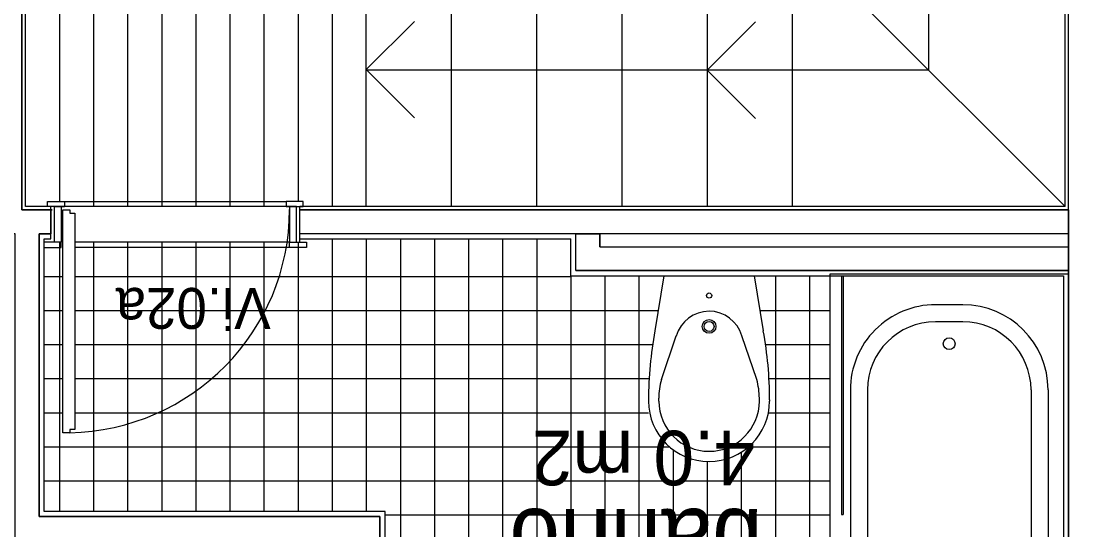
# Model space of a CAD drawing. Extents: x 1278 to 1356, y -253.7 to -224.
# Drawn here: x 1336.931 to 1340.025, y -239.375 to -237.882 of the extents above; entities that cross this region are included whole.
import ezdxf

# ---------------------------------------------------------------- set-up
doc = ezdxf.new("R2010")
doc.units = 0
for name, color, linetype in [('Level 1', 7, 'Continuous'), ('Level 10', 7, 'Continuous'), ('Level 11', 7, 'Continuous'), ('Level 13', 7, 'Continuous'), ('Level 2', 7, 'Continuous'), ('Level 36', 7, 'Continuous'), ('Level 4', 7, 'Continuous'), ('Level 40', 7, 'Continuous'), ('Level 60', 7, 'Continuous'), ('Level 65', 7, 'Continuous'), ('Level 66', 7, 'Continuous'), ('Level 67', 7, 'Continuous')]:
    doc.layers.add(name, color=color, linetype=linetype)

msp = doc.modelspace()

# ---------------------------------------------------------------- linework, layer by layer
at = {"layer": 'Level 1'}
for p, q in [((1340.0033, -238.4357), (1340.0033, -235.7107)), ((1336.9333, -238.4357), (1336.9333, -236.6557)), ((1337.0183, -238.4357), (1336.9333, -238.4357)), ((1337.0183, -238.5207), (1337.0183, -238.4257)), ((1337.7483, -238.5307), (1337.7483, -238.4257)), ((1340.0033, -238.4357), (1337.7483, -238.4357)), ((1336.9833, -239.3357), (1336.9833, -238.5057)), ((1336.9833, -238.5057), (1337.0183, -238.5057)), ((1338.5583, -238.5057), (1337.7483, -238.5057)), ((1340.0033, -238.5057), (1338.6283, -238.5057)), ((1340.0033, -238.614), (1340.0033, -240.234)), ((1337.9833, -239.3357), (1336.9833, -239.3357)), ((1337.9833, -240.234), (1337.9833, -239.3357))]:
    msp.add_line(p, q, dxfattribs=at)
at = {"layer": 'Level 10'}
for p, q in [((1337.0433, -235.7207), (1337.0433, -238.4107)), ((1337.1433, -235.7207), (1337.1433, -238.4257)), ((1337.2433, -235.7207), (1337.2433, -238.4257)), ((1337.3433, -235.7207), (1337.3433, -238.4257)), ((1337.4433, -235.7207), (1337.4433, -238.4257)), ((1337.5433, -235.7207), (1337.5433, -238.4257)), ((1337.6433, -235.7207), (1337.6433, -238.4257)), ((1337.7433, -235.7207), (1337.7433, -238.4107)), ((1337.8433, -236.6557), (1337.8433, -238.4257)), ((1337.7083, -238.4257), (1337.0583, -238.4257)), ((1337.8433, -238.5207), (1337.8433, -239.3207)), ((1337.9433, -238.5207), (1337.9433, -239.3207)), ((1338.0433, -238.5207), (1338.0433, -239.669)), ((1338.1433, -238.5207), (1338.1433, -239.669)), ((1338.2433, -238.5207), (1338.2433, -239.669)), ((1338.3433, -238.5207), (1338.3433, -239.669)), ((1338.4433, -238.5207), (1338.4433, -239.669)), ((1337.0433, -238.5307), (1337.0433, -239.3207)), ((1337.7183, -238.5307), (1337.0883, -238.5307)), ((1337.1433, -238.5307), (1337.1433, -239.3207)), ((1337.2433, -238.5307), (1337.2433, -239.3207)), ((1337.3433, -238.5307), (1337.3433, -239.3207)), ((1337.4433, -238.5307), (1337.4433, -239.3207)), ((1337.5433, -238.5307), (1337.5433, -239.3207)), ((1337.6433, -238.5307), (1337.6433, -239.3207)), ((1337.7433, -238.5307), (1337.7433, -239.3207)), ((1336.9983, -238.6307), (1337.0533, -238.6307)), ((1337.0883, -238.6307), (1338.5433, -238.6307)), ((1338.5433, -238.629), (1338.5433, -239.669)), ((1338.6433, -238.629), (1338.6433, -240.219)), ((1338.7433, -238.629), (1338.7433, -240.219)), ((1339.1433, -238.629), (1339.1433, -240.219)), ((1339.2433, -238.629), (1339.2433, -240.219)), ((1336.9983, -238.7307), (1337.0533, -238.7307)), ((1337.0883, -238.7307), (1338.7999, -238.7307)), ((1339.098, -238.7307), (1339.3033, -238.7307)), ((1336.9983, -238.8307), (1337.0533, -238.8307)), ((1337.0883, -238.8307), (1338.7834, -238.8307)), ((1339.1145, -238.8307), (1339.3033, -238.8307)), ((1336.9983, -238.9307), (1337.0533, -238.9307)), ((1337.0883, -238.9307), (1338.7732, -238.9307)), ((1339.1247, -238.9307), (1339.3033, -238.9307)), ((1336.9983, -239.0307), (1337.0533, -239.0307)), ((1337.0883, -239.0307), (1338.7714, -239.0307)), ((1339.1231, -239.0307), (1339.3033, -239.0307)), ((1336.9983, -239.1307), (1338.8328, -239.1307)), ((1338.8433, -239.1391), (1338.8433, -239.7067)), ((1339.0433, -239.1468), (1339.0433, -239.7067)), ((1339.065, -239.1307), (1339.3033, -239.1307)), ((1338.9433, -239.1739), (1338.9433, -239.6759)), ((1336.9983, -239.2307), (1339.3033, -239.2307)), ((1337.9983, -239.3307), (1339.3033, -239.3307))]:
    msp.add_line(p, q, dxfattribs=at)
at = {"layer": 'Level 11'}
for p, q in [((1338.8166, -238.629), (1338.79, -238.791)), ((1338.8166, -238.629), (1339.0812, -238.629)), ((1339.0812, -238.629), (1339.1079, -238.791)), ((1340.0033, -238.624), (1339.3033, -238.624)), ((1339.3033, -238.624), (1339.3033, -240.224)), ((1340.0033, -238.624), (1340.0033, -240.224)), ((1339.6933, -238.714), (1339.6133, -238.714)), ((1339.6933, -238.764), (1339.6133, -238.764)), ((1338.8091, -238.9335), (1338.8528, -238.8055)), ((1339.0887, -238.9335), (1339.0451, -238.8055)), ((1338.7714, -238.9931), (1338.7714, -238.9968)), ((1338.8014, -238.9965), (1338.8014, -238.9884)), ((1339.0964, -238.9965), (1339.0964, -238.9884)), ((1339.1264, -238.9931), (1339.1264, -238.9968)), ((1339.3633, -238.964), (1339.3633, -240.014)), ((1339.4133, -238.964), (1339.4133, -239.914)), ((1339.8933, -238.964), (1339.8933, -239.914)), ((1339.9433, -238.964), (1339.9433, -240.014))]:
    msp.add_line(p, q, dxfattribs=at)
for centre, radius in [((1338.9489, -238.687), 0.00766), ((1338.9489, -238.7778), 0.02), ((1338.9489, -238.7778), 0.0146), ((1339.6533, -238.8284), 0.0173)]:
    msp.add_circle(centre, radius, dxfattribs=at)
for centre, radius, start, end in [((1339.6133, -238.964), 0.25, 89.9999, 180), ((1339.6933, -238.964), 0.25, 0.0001, 90.0001), ((1338.9489, -238.833), 0.1, 15.9317, 164.1953), ((1339.6133, -238.964), 0.2, 90, 180), ((1339.6933, -238.964), 0.2, 360, 90), ((1339.0014, -238.9884), 0.2, 164.0693, 180.0006), ((1338.8964, -238.9884), 0.2, 0.0017, 15.9319), ((1338.9489, -238.9965), 0.1775, 180.0002, 359.9999), ((1338.9489, -238.9965), 0.1475, 180.0002, 359.9999)]:
    msp.add_arc(centre, radius, start, end, dxfattribs=at)
for centre, major_axis, start_param, end_param in [((1340.1714, -238.9931), (-1.4, 0), 6.120269, 6.283187), ((1337.7264, -238.9931), (1.4, 0), 6.283183, 6.446102)]:
    msp.add_ellipse(centre, major_axis=major_axis, ratio=0.88995, start_param=start_param, end_param=end_param, dxfattribs=at)
at = {"layer": 'Level 13'}
for p, q in [((1337.0083, -238.4107), (1337.0583, -238.4107)), ((1337.0083, -238.4257), (1337.0083, -238.4107)), ((1337.0583, -238.4257), (1337.0083, -238.4257)), ((1337.0283, -238.5307), (1337.0283, -238.4257)), ((1337.0283, -238.4257), (1337.0583, -238.4257)), ((1337.0483, -238.4257), (1337.0483, -238.5307)), ((1337.0533, -239.0901), (1337.0533, -238.4351)), ((1337.0533, -238.4351), (1337.0733, -238.4351)), ((1337.0583, -238.4107), (1337.0583, -238.4257)), ((1337.0733, -238.4351), (1337.0733, -238.4451)), ((1337.7583, -238.4107), (1337.7083, -238.4107)), ((1337.7083, -238.4107), (1337.7083, -238.4257)), ((1337.7383, -238.4257), (1337.7083, -238.4257)), ((1337.7083, -238.4257), (1337.7583, -238.4257)), ((1337.7183, -238.4257), (1337.7183, -238.5307)), ((1337.7383, -238.5307), (1337.7383, -238.4257)), ((1337.7583, -238.4257), (1337.7583, -238.4107)), ((1337.0733, -238.4451), (1337.0883, -238.4451)), ((1337.0883, -238.4451), (1337.0883, -239.0801)), ((1337.0483, -238.5307), (1336.9983, -238.5307)), ((1336.9983, -238.5457), (1337.0483, -238.5457)), ((1337.0483, -238.5307), (1337.0283, -238.5307)), ((1337.0483, -238.5457), (1337.0483, -238.5307)), ((1337.7183, -238.5457), (1337.7183, -238.5307)), ((1337.7183, -238.5307), (1337.7383, -238.5307)), ((1337.7183, -238.5307), (1337.7683, -238.5307)), ((1337.7683, -238.5457), (1337.7183, -238.5457)), ((1337.7683, -238.5307), (1337.7683, -238.5457)), ((1337.0733, -239.0801), (1337.0733, -239.0898)), ((1337.0883, -239.0801), (1337.0733, -239.0801)), ((1337.0733, -239.0901), (1337.0533, -239.0901))]:
    msp.add_line(p, q, dxfattribs=at)
at = {"layer": 'Level 2'}
for p, q in [((1339.5933, -238.0257), (1339.5933, -237.2257)), ((1339.1933, -237.6257), (1339.9933, -238.4257)), ((1337.9433, -238.424), (1337.9433, -237.6557)), ((1338.1933, -238.424), (1338.1933, -237.6557)), ((1338.4433, -238.424), (1338.4433, -237.6557)), ((1338.6933, -237.6557), (1338.6933, -238.424)), ((1338.9433, -237.654), (1338.9433, -238.424)), ((1339.1933, -238.4257), (1339.1933, -237.6557)), ((1338.0847, -237.8826), (1337.9433, -238.024)), ((1339.0847, -237.8843), (1338.9433, -238.0257)), ((1338.0847, -238.1654), (1337.9433, -238.024)), ((1339.5933, -238.0257), (1337.9433, -238.0257)), ((1339.0847, -238.1672), (1338.9433, -238.0257)), ((1339.5933, -238.0257), (1338.9433, -238.0257))]:
    msp.add_line(p, q, dxfattribs=at)
at = {"layer": 'Level 36'}
for p, q in [((1339.3377, -238.629), (1339.3377, -239.329)), ((1339.3427, -238.629), (1339.3427, -239.329)), ((1339.3377, -239.329), (1339.3427, -239.329))]:
    msp.add_line(p, q, dxfattribs=at)
at = {"layer": 'Level 4'}
for p, q in [((1337.0583, -238.4107), (1337.7083, -238.4107)), ((1337.7183, -238.5457), (1337.0883, -238.5457))]:
    msp.add_line(p, q, dxfattribs=at)
msp.add_ellipse((1337.0596, -238.435), major_axis=(-0.6586, 0), ratio=0.994279, start_param=1.591512, end_param=3.141593, dxfattribs=at)
at = {"layer": 'Level 65'}
for p, q in [((1336.9433, -238.4257), (1336.9433, -236.6557)), ((1339.9933, -238.4257), (1339.9933, -236.8257)), ((1339.9933, -238.4257), (1339.9933, -236.8257)), ((1337.0183, -238.4257), (1336.9433, -238.4257)), ((1339.9933, -238.4257), (1337.7483, -238.4257)), ((1336.9983, -239.3207), (1336.9983, -238.5207)), ((1336.9983, -238.5207), (1337.0183, -238.5207)), ((1337.7483, -238.5207), (1338.5433, -238.5207)), ((1338.5433, -238.629), (1338.5433, -238.5207)), ((1338.5433, -238.629), (1339.9883, -238.629)), ((1339.9883, -238.629), (1339.9883, -240.219)), ((1337.9983, -239.3207), (1336.9983, -239.3207)), ((1337.9983, -240.219), (1337.9983, -239.3207))]:
    msp.add_line(p, q, dxfattribs=at)
at = {"layer": 'Level 66'}
for p, q in [((1338.5583, -238.614), (1338.5583, -238.5057)), ((1338.6283, -238.544), (1338.6283, -238.5057)), ((1340.0033, -238.5057), (1340.0033, -238.544)), ((1338.6283, -238.544), (1340.0033, -238.544)), ((1338.5583, -238.614), (1340.0033, -238.614))]:
    msp.add_line(p, q, dxfattribs=at)
at = {"layer": 'Level 67'}
for points in [[(1340.0033, -240.234), (1340.0033, -240.304), (1337.9133, -240.304), (1337.9133, -239.4057), (1336.9133, -239.4057), (1336.9133, -238.5057), (1335.7533, -238.5057), (1335.7533, -238.244), (1334.8332, -238.244), (1334.8333, -238.174), (1335.8241, -238.174), (1335.8241, -238.4357), (1336.8533, -238.4357), (1336.8533, -236.6557), (1336.9333, -236.6557), (1336.9333, -238.4357), (1337.022, -238.4357), (1337.0183, -238.4357), (1337.0183, -238.5057), (1336.9833, -238.5057), (1336.9833, -239.3357), (1337.9833, -239.3357), (1337.9833, -240.234), (1340.0033, -240.234)], [(1340.0733, -242.1713), (1340.0033, -242.1713), (1340.0033, -236.7713), (1340.0733, -236.7713)], [(1340.0033, -238.4357), (1340.0033, -238.5057), (1337.7483, -238.5057), (1337.7483, -238.4357)], [(1338.6283, -238.5057), (1338.6283, -238.544), (1340.0033, -238.544), (1340.0033, -238.614), (1338.5583, -238.614), (1338.5583, -238.5057)]]:
    msp.add_lwpolyline(points, close=True, dxfattribs=at)

# ---------------------------------------------------------------- texts
at = {"layer": 'Level 40'}
msp.add_text('Vi.02a', height=0.12, rotation=180, dxfattribs=at).set_placement((1337.663, -238.6648))
at = {"layer": 'Level 60'}
for s, height, p in [('4.0 m2', 0.16, (1339.0833, -239.0837)), ('banho', 0.2, (1339.1067, -239.3132))]:
    msp.add_text(s, height=height, rotation=180, dxfattribs=at).set_placement(p)

doc.saveas('drawing.dxf')
